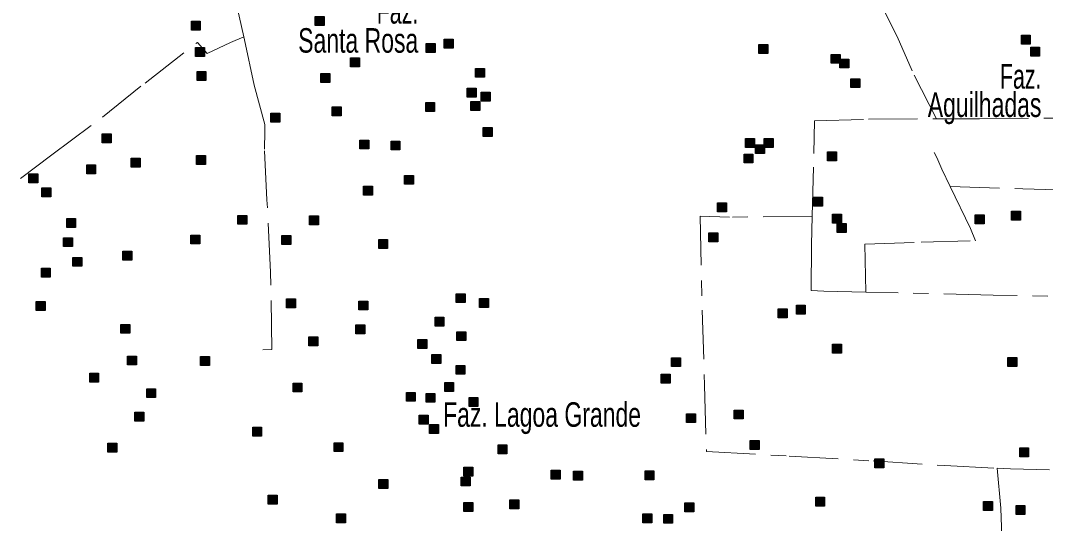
# Model space of a CAD drawing. Extents: x 445.6 to 500, y 8618.1 to 8673.4.
# Drawn here: x 485.76 to 492.44, y 8640.98 to 8644.26 of the extents above; entities that cross this region are included whole.
import ezdxf
from ezdxf.enums import TextEntityAlignment as Align

# ---------------------------------------------------------------- set-up
doc = ezdxf.new("R2010")
doc.units = 0
doc.header["$LTSCALE"] = 0.064
doc.linetypes.add('DOT_DASHED', pattern=[7.7, 5, -1.2, 0.3, -1.2])
doc.layers.add('2', color=7, linetype='Continuous', lineweight=25)
doc.layers.add('22', color=7, linetype='DOT_DASHED', lineweight=13)
doc.layers.add('61', color=7, linetype='Continuous')

msp = doc.modelspace()

# ---------------------------------------------------------------- hatches: boundary and pattern name
at = {"layer": '2'}
for points in [[(487.68, 8644.2843), (487.738, 8644.2843), (487.738, 8644.2263), (487.68, 8644.2263)], [(486.8722, 8644.2533), (486.9302, 8644.2533), (486.9302, 8644.1953), (486.8722, 8644.1953)], [(488.5211, 8644.1352), (488.5791, 8644.1352), (488.5791, 8644.0772), (488.5211, 8644.0772)], [(492.2832, 8644.1613), (492.3412, 8644.1613), (492.3412, 8644.1033), (492.2832, 8644.1033)], [(486.8998, 8644.0813), (486.9578, 8644.0813), (486.9578, 8644.0233), (486.8998, 8644.0233)], [(488.4029, 8644.1081), (488.4609, 8644.1081), (488.4609, 8644.0501), (488.4029, 8644.0501)], [(490.5725, 8644.1015), (490.6305, 8644.1015), (490.6305, 8644.0435), (490.5725, 8644.0435)], [(492.344, 8644.0834), (492.402, 8644.0834), (492.402, 8644.0254), (492.344, 8644.0254)], [(487.9103, 8644.0133), (487.9683, 8644.0133), (487.9683, 8643.9553), (487.9103, 8643.9553)], [(491.0429, 8644.037), (491.1009, 8644.037), (491.1009, 8643.979), (491.0429, 8643.979)], [(491.1003, 8644.0065), (491.1583, 8644.0065), (491.1583, 8643.9485), (491.1003, 8643.9485)], [(486.9088, 8643.9252), (486.9668, 8643.9252), (486.9668, 8643.8672), (486.9088, 8643.8672)], [(488.7243, 8643.9455), (488.7823, 8643.9455), (488.7823, 8643.8875), (488.7243, 8643.8875)], [(487.7161, 8643.9117), (487.7741, 8643.9117), (487.7741, 8643.8537), (487.7161, 8643.8537)], [(491.1712, 8643.8778), (491.2292, 8643.8778), (491.2292, 8643.8198), (491.1712, 8643.8198)], [(488.6703, 8643.8168), (488.7283, 8643.8168), (488.7283, 8643.7588), (488.6703, 8643.7588)], [(488.7615, 8643.7897), (488.8195, 8643.7897), (488.8195, 8643.7317), (488.7615, 8643.7317)], [(488.6939, 8643.7287), (488.7519, 8643.7287), (488.7519, 8643.6707), (488.6939, 8643.6707)], [(487.7904, 8643.6948), (487.8484, 8643.6948), (487.8484, 8643.6368), (487.7904, 8643.6368)], [(488.4001, 8643.7219), (488.4581, 8643.7219), (488.4581, 8643.6639), (488.4001, 8643.6639)], [(487.3899, 8643.6529), (487.4479, 8643.6529), (487.4479, 8643.5949), (487.3899, 8643.5949)], [(488.775, 8643.5593), (488.833, 8643.5593), (488.833, 8643.5013), (488.775, 8643.5013)], [(486.2907, 8643.5187), (486.3487, 8643.5187), (486.3487, 8643.4607), (486.2907, 8643.4607)], [(487.9711, 8643.478), (488.0291, 8643.478), (488.0291, 8643.42), (487.9711, 8643.42)], [(488.1737, 8643.4712), (488.2317, 8643.4712), (488.2317, 8643.4132), (488.1737, 8643.4132)], [(490.4856, 8643.4882), (490.5436, 8643.4882), (490.5436, 8643.4302), (490.4856, 8643.4302)], [(490.6072, 8643.4882), (490.6652, 8643.4882), (490.6652, 8643.4302), (490.6072, 8643.4302)], [(490.5497, 8643.4475), (490.6077, 8643.4475), (490.6077, 8643.3895), (490.5497, 8643.3895)], [(491.0192, 8643.4001), (491.0772, 8643.4001), (491.0772, 8643.3421), (491.0192, 8643.3421)], [(486.4798, 8643.3594), (486.5378, 8643.3594), (486.5378, 8643.3014), (486.4798, 8643.3014)], [(486.9054, 8643.3764), (486.9634, 8643.3764), (486.9634, 8643.3184), (486.9054, 8643.3184)], [(490.4754, 8643.3865), (490.5334, 8643.3865), (490.5334, 8643.3285), (490.4754, 8643.3285)], [(485.8128, 8643.2578), (485.8708, 8643.2578), (485.8708, 8643.1998), (485.8128, 8643.1998)], [(486.1893, 8643.3154), (486.2473, 8643.3154), (486.2473, 8643.2574), (486.1893, 8643.2574)], [(488.2616, 8643.2476), (488.3196, 8643.2476), (488.3196, 8643.1896), (488.2616, 8643.1896)], [(485.8973, 8643.1663), (485.9553, 8643.1663), (485.9553, 8643.1083), (485.8973, 8643.1083)], [(487.9947, 8643.1765), (488.0527, 8643.1765), (488.0527, 8643.1185), (487.9947, 8643.1185)], [(490.3032, 8643.0681), (490.3612, 8643.0681), (490.3612, 8643.0101), (490.3032, 8643.0101)], [(490.928, 8643.1054), (490.986, 8643.1054), (490.986, 8643.0474), (490.928, 8643.0474)], [(491.053, 8642.9936), (491.111, 8642.9936), (491.111, 8642.9356), (491.053, 8642.9356)], [(491.9828, 8642.9903), (492.0408, 8642.9903), (492.0408, 8642.9323), (491.9828, 8642.9323)], [(492.2192, 8643.014), (492.2772, 8643.014), (492.2772, 8642.956), (492.2192, 8642.956)], [(486.0594, 8642.9665), (486.1174, 8642.9665), (486.1174, 8642.9085), (486.0594, 8642.9085)], [(487.1756, 8642.9868), (487.2336, 8642.9868), (487.2336, 8642.9288), (487.1756, 8642.9288)], [(487.6418, 8642.9834), (487.6998, 8642.9834), (487.6998, 8642.9254), (487.6418, 8642.9254)], [(491.0834, 8642.9326), (491.1414, 8642.9326), (491.1414, 8642.8746), (491.0834, 8642.8746)], [(486.8683, 8642.858), (486.9263, 8642.858), (486.9263, 8642.8), (486.8683, 8642.8)], [(487.4627, 8642.8547), (487.5207, 8642.8547), (487.5207, 8642.7967), (487.4627, 8642.7967)], [(490.2458, 8642.8728), (490.3038, 8642.8728), (490.3038, 8642.8148), (490.2458, 8642.8148)], [(486.0391, 8642.8411), (486.0971, 8642.8411), (486.0971, 8642.7831), (486.0391, 8642.7831)], [(488.0933, 8642.8287), (488.1513, 8642.8287), (488.1513, 8642.7707), (488.0933, 8642.7707)], [(486.4258, 8642.753), (486.4838, 8642.753), (486.4838, 8642.695), (486.4258, 8642.695)], [(486.0999, 8642.7124), (486.1579, 8642.7124), (486.1579, 8642.6544), (486.0999, 8642.6544)], [(485.894, 8642.6421), (485.952, 8642.6421), (485.952, 8642.5841), (485.894, 8642.5841)], [(488.5993, 8642.4752), (488.6573, 8642.4752), (488.6573, 8642.4172), (488.5993, 8642.4172)], [(485.8602, 8642.425), (485.9182, 8642.425), (485.9182, 8642.367), (485.8602, 8642.367)], [(487.4931, 8642.4413), (487.5511, 8642.4413), (487.5511, 8642.3833), (487.4931, 8642.3833)], [(487.9643, 8642.4278), (488.0223, 8642.4278), (488.0223, 8642.3698), (487.9643, 8642.3698)], [(488.7513, 8642.4447), (488.8093, 8642.4447), (488.8093, 8642.3867), (488.7513, 8642.3867)], [(490.8166, 8642.4007), (490.8746, 8642.4007), (490.8746, 8642.3427), (490.8166, 8642.3427)], [(488.4609, 8642.3228), (488.5189, 8642.3228), (488.5189, 8642.2648), (488.4609, 8642.2648)], [(490.6984, 8642.377), (490.7564, 8642.377), (490.7564, 8642.319), (490.6984, 8642.319)], [(486.4123, 8642.2753), (486.4703, 8642.2753), (486.4703, 8642.2173), (486.4123, 8642.2173)], [(487.9441, 8642.2719), (488.0021, 8642.2719), (488.0021, 8642.2139), (487.9441, 8642.2139)], [(487.6384, 8642.194), (487.6964, 8642.194), (487.6964, 8642.136), (487.6384, 8642.136)], [(488.6027, 8642.2279), (488.6607, 8642.2279), (488.6607, 8642.1699), (488.6027, 8642.1699)], [(488.3494, 8642.1771), (488.4074, 8642.1771), (488.4074, 8642.1191), (488.3494, 8642.1191)], [(491.053, 8642.1466), (491.111, 8642.1466), (491.111, 8642.0886), (491.053, 8642.0886)], [(486.4562, 8642.0687), (486.5142, 8642.0687), (486.5142, 8642.0107), (486.4562, 8642.0107)], [(486.9324, 8642.0653), (486.9904, 8642.0653), (486.9904, 8642.0073), (486.9324, 8642.0073)], [(488.4406, 8642.0788), (488.4986, 8642.0788), (488.4986, 8642.0208), (488.4406, 8642.0208)], [(490.0021, 8642.0584), (490.0601, 8642.0584), (490.0601, 8642.0004), (490.0021, 8642.0004)], [(492.1958, 8642.0589), (492.2538, 8642.0589), (492.2538, 8642.0009), (492.1958, 8642.0009)], [(488.5977, 8642.0082), (488.6557, 8642.0082), (488.6557, 8641.9502), (488.5977, 8641.9502)], [(486.2092, 8641.9573), (486.2672, 8641.9573), (486.2672, 8641.8993), (486.2092, 8641.8993)], [(489.9345, 8641.9506), (489.9925, 8641.9506), (489.9925, 8641.8926), (489.9345, 8641.8926)], [(486.5807, 8641.8557), (486.6387, 8641.8557), (486.6387, 8641.7977), (486.5807, 8641.7977)], [(487.535, 8641.893), (487.593, 8641.893), (487.593, 8641.835), (487.535, 8641.835)], [(488.5234, 8641.8964), (488.5814, 8641.8964), (488.5814, 8641.8384), (488.5234, 8641.8384)], [(488.2734, 8641.832), (488.3314, 8641.832), (488.3314, 8641.774), (488.2734, 8641.774)], [(488.4018, 8641.8252), (488.4598, 8641.8252), (488.4598, 8641.7672), (488.4018, 8641.7672)], [(488.6821, 8641.7981), (488.7401, 8641.7981), (488.7401, 8641.7401), (488.6821, 8641.7401)], [(486.5035, 8641.7022), (486.5615, 8641.7022), (486.5615, 8641.6442), (486.5035, 8641.6442)], [(488.3579, 8641.6829), (488.4159, 8641.6829), (488.4159, 8641.6249), (488.3579, 8641.6249)], [(490.1, 8641.6931), (490.158, 8641.6931), (490.158, 8641.6351), (490.1, 8641.6351)], [(490.4107, 8641.7169), (490.4687, 8641.7169), (490.4687, 8641.6589), (490.4107, 8641.6589)], [(487.2716, 8641.605), (487.3296, 8641.605), (487.3296, 8641.547), (487.2716, 8641.547)], [(488.4254, 8641.6219), (488.4834, 8641.6219), (488.4834, 8641.5639), (488.4254, 8641.5639)], [(490.5154, 8641.517), (490.5734, 8641.517), (490.5734, 8641.459), (490.5154, 8641.459)], [(486.328, 8641.5), (486.386, 8641.5), (486.386, 8641.442), (486.328, 8641.442)], [(487.8019, 8641.5034), (487.8599, 8641.5034), (487.8599, 8641.4454), (487.8019, 8641.4454)], [(488.8713, 8641.4898), (488.9293, 8641.4898), (488.9293, 8641.4318), (488.8713, 8641.4318)], [(492.2725, 8641.4695), (492.3305, 8641.4695), (492.3305, 8641.4115), (492.2725, 8641.4115)], [(491.3278, 8641.3983), (491.3858, 8641.3983), (491.3858, 8641.3403), (491.3278, 8641.3403)], [(488.6483, 8641.3441), (488.7063, 8641.3441), (488.7063, 8641.2861), (488.6483, 8641.2861)], [(489.2184, 8641.3239), (489.2764, 8641.3239), (489.2764, 8641.2659), (489.2184, 8641.2659)], [(489.3636, 8641.3171), (489.4216, 8641.3171), (489.4216, 8641.2591), (489.3636, 8641.2591)], [(489.8298, 8641.3205), (489.8878, 8641.3205), (489.8878, 8641.2625), (489.8298, 8641.2625)], [(488.0944, 8641.2628), (488.1524, 8641.2628), (488.1524, 8641.2048), (488.0944, 8641.2048)], [(488.6314, 8641.2798), (488.6894, 8641.2798), (488.6894, 8641.2218), (488.6314, 8641.2218)], [(487.3729, 8641.1612), (487.4309, 8641.1612), (487.4309, 8641.1032), (487.3729, 8641.1032)], [(488.9482, 8641.1308), (489.0062, 8641.1308), (489.0062, 8641.0728), (488.9482, 8641.0728)], [(490.9427, 8641.1476), (491.0007, 8641.1476), (491.0007, 8641.0896), (490.9427, 8641.0896)], [(492.0361, 8641.1205), (492.0941, 8641.1205), (492.0941, 8641.0625), (492.0361, 8641.0625)], [(488.6483, 8641.1138), (488.7063, 8641.1138), (488.7063, 8641.0558), (488.6483, 8641.0558)], [(490.0899, 8641.1104), (490.1479, 8641.1104), (490.1479, 8641.0524), (490.0899, 8641.0524)], [(492.2489, 8641.0934), (492.3069, 8641.0934), (492.3069, 8641.0354), (492.2489, 8641.0354)], [(487.8188, 8641.0392), (487.8768, 8641.0392), (487.8768, 8640.9812), (487.8188, 8640.9812)], [(489.8163, 8641.0393), (489.8743, 8641.0393), (489.8743, 8640.9813), (489.8163, 8640.9813)], [(489.9514, 8641.0359), (490.0094, 8641.0359), (490.0094, 8640.9779), (489.9514, 8640.9779)]]:
    msp.add_hatch(color=256, dxfattribs=at).paths.add_polyline_path(points)

# ---------------------------------------------------------------- linework, layer by layer
for points in [[(487.68, 8644.2843), (487.738, 8644.2843), (487.738, 8644.2263), (487.68, 8644.2263)], [(486.8722, 8644.2533), (486.9302, 8644.2533), (486.9302, 8644.1953), (486.8722, 8644.1953)], [(488.5211, 8644.1352), (488.5791, 8644.1352), (488.5791, 8644.0772), (488.5211, 8644.0772)], [(492.2832, 8644.1613), (492.3412, 8644.1613), (492.3412, 8644.1033), (492.2832, 8644.1033)], [(486.8998, 8644.0813), (486.9578, 8644.0813), (486.9578, 8644.0233), (486.8998, 8644.0233)], [(488.4029, 8644.1081), (488.4609, 8644.1081), (488.4609, 8644.0501), (488.4029, 8644.0501)], [(490.5725, 8644.1015), (490.6305, 8644.1015), (490.6305, 8644.0435), (490.5725, 8644.0435)], [(492.344, 8644.0834), (492.402, 8644.0834), (492.402, 8644.0254), (492.344, 8644.0254)], [(487.9103, 8644.0133), (487.9683, 8644.0133), (487.9683, 8643.9553), (487.9103, 8643.9553)], [(491.0429, 8644.037), (491.1009, 8644.037), (491.1009, 8643.979), (491.0429, 8643.979)], [(491.1003, 8644.0065), (491.1583, 8644.0065), (491.1583, 8643.9485), (491.1003, 8643.9485)], [(486.9088, 8643.9252), (486.9668, 8643.9252), (486.9668, 8643.8672), (486.9088, 8643.8672)], [(488.7243, 8643.9455), (488.7823, 8643.9455), (488.7823, 8643.8875), (488.7243, 8643.8875)], [(487.7161, 8643.9117), (487.7741, 8643.9117), (487.7741, 8643.8537), (487.7161, 8643.8537)], [(491.1712, 8643.8778), (491.2292, 8643.8778), (491.2292, 8643.8198), (491.1712, 8643.8198)], [(488.6703, 8643.8168), (488.7283, 8643.8168), (488.7283, 8643.7588), (488.6703, 8643.7588)], [(488.7615, 8643.7897), (488.8195, 8643.7897), (488.8195, 8643.7317), (488.7615, 8643.7317)], [(488.6939, 8643.7287), (488.7519, 8643.7287), (488.7519, 8643.6707), (488.6939, 8643.6707)], [(487.7904, 8643.6948), (487.8484, 8643.6948), (487.8484, 8643.6368), (487.7904, 8643.6368)], [(488.4001, 8643.7219), (488.4581, 8643.7219), (488.4581, 8643.6639), (488.4001, 8643.6639)], [(487.3899, 8643.6529), (487.4479, 8643.6529), (487.4479, 8643.5949), (487.3899, 8643.5949)], [(488.775, 8643.5593), (488.833, 8643.5593), (488.833, 8643.5013), (488.775, 8643.5013)], [(486.2907, 8643.5187), (486.3487, 8643.5187), (486.3487, 8643.4607), (486.2907, 8643.4607)], [(487.9711, 8643.478), (488.0291, 8643.478), (488.0291, 8643.42), (487.9711, 8643.42)], [(488.1737, 8643.4712), (488.2317, 8643.4712), (488.2317, 8643.4132), (488.1737, 8643.4132)], [(490.4856, 8643.4882), (490.5436, 8643.4882), (490.5436, 8643.4302), (490.4856, 8643.4302)], [(490.6072, 8643.4882), (490.6652, 8643.4882), (490.6652, 8643.4302), (490.6072, 8643.4302)], [(490.5497, 8643.4475), (490.6077, 8643.4475), (490.6077, 8643.3895), (490.5497, 8643.3895)], [(491.0192, 8643.4001), (491.0772, 8643.4001), (491.0772, 8643.3421), (491.0192, 8643.3421)], [(486.4798, 8643.3594), (486.5378, 8643.3594), (486.5378, 8643.3014), (486.4798, 8643.3014)], [(486.9054, 8643.3764), (486.9634, 8643.3764), (486.9634, 8643.3184), (486.9054, 8643.3184)], [(490.4754, 8643.3865), (490.5334, 8643.3865), (490.5334, 8643.3285), (490.4754, 8643.3285)], [(485.8128, 8643.2578), (485.8708, 8643.2578), (485.8708, 8643.1998), (485.8128, 8643.1998)], [(486.1893, 8643.3154), (486.2473, 8643.3154), (486.2473, 8643.2574), (486.1893, 8643.2574)], [(488.2616, 8643.2476), (488.3196, 8643.2476), (488.3196, 8643.1896), (488.2616, 8643.1896)], [(485.8973, 8643.1663), (485.9553, 8643.1663), (485.9553, 8643.1083), (485.8973, 8643.1083)], [(487.9947, 8643.1765), (488.0527, 8643.1765), (488.0527, 8643.1185), (487.9947, 8643.1185)], [(490.3032, 8643.0681), (490.3612, 8643.0681), (490.3612, 8643.0101), (490.3032, 8643.0101)], [(490.928, 8643.1054), (490.986, 8643.1054), (490.986, 8643.0474), (490.928, 8643.0474)], [(491.053, 8642.9936), (491.111, 8642.9936), (491.111, 8642.9356), (491.053, 8642.9356)], [(491.9828, 8642.9903), (492.0408, 8642.9903), (492.0408, 8642.9323), (491.9828, 8642.9323)], [(492.2192, 8643.014), (492.2772, 8643.014), (492.2772, 8642.956), (492.2192, 8642.956)], [(486.0594, 8642.9665), (486.1174, 8642.9665), (486.1174, 8642.9085), (486.0594, 8642.9085)], [(487.1756, 8642.9868), (487.2336, 8642.9868), (487.2336, 8642.9288), (487.1756, 8642.9288)], [(487.6418, 8642.9834), (487.6998, 8642.9834), (487.6998, 8642.9254), (487.6418, 8642.9254)], [(491.0834, 8642.9326), (491.1414, 8642.9326), (491.1414, 8642.8746), (491.0834, 8642.8746)], [(486.8683, 8642.858), (486.9263, 8642.858), (486.9263, 8642.8), (486.8683, 8642.8)], [(487.4627, 8642.8547), (487.5207, 8642.8547), (487.5207, 8642.7967), (487.4627, 8642.7967)], [(490.2458, 8642.8728), (490.3038, 8642.8728), (490.3038, 8642.8148), (490.2458, 8642.8148)], [(486.0391, 8642.8411), (486.0971, 8642.8411), (486.0971, 8642.7831), (486.0391, 8642.7831)], [(488.0933, 8642.8287), (488.1513, 8642.8287), (488.1513, 8642.7707), (488.0933, 8642.7707)], [(486.4258, 8642.753), (486.4838, 8642.753), (486.4838, 8642.695), (486.4258, 8642.695)], [(486.0999, 8642.7124), (486.1579, 8642.7124), (486.1579, 8642.6544), (486.0999, 8642.6544)], [(485.894, 8642.6421), (485.952, 8642.6421), (485.952, 8642.5841), (485.894, 8642.5841)], [(488.5993, 8642.4752), (488.6573, 8642.4752), (488.6573, 8642.4172), (488.5993, 8642.4172)], [(485.8602, 8642.425), (485.9182, 8642.425), (485.9182, 8642.367), (485.8602, 8642.367)], [(487.4931, 8642.4413), (487.5511, 8642.4413), (487.5511, 8642.3833), (487.4931, 8642.3833)], [(487.9643, 8642.4278), (488.0223, 8642.4278), (488.0223, 8642.3698), (487.9643, 8642.3698)], [(488.7513, 8642.4447), (488.8093, 8642.4447), (488.8093, 8642.3867), (488.7513, 8642.3867)], [(490.8166, 8642.4007), (490.8746, 8642.4007), (490.8746, 8642.3427), (490.8166, 8642.3427)], [(488.4609, 8642.3228), (488.5189, 8642.3228), (488.5189, 8642.2648), (488.4609, 8642.2648)], [(490.6984, 8642.377), (490.7564, 8642.377), (490.7564, 8642.319), (490.6984, 8642.319)], [(486.4123, 8642.2753), (486.4703, 8642.2753), (486.4703, 8642.2173), (486.4123, 8642.2173)], [(487.9441, 8642.2719), (488.0021, 8642.2719), (488.0021, 8642.2139), (487.9441, 8642.2139)], [(487.6384, 8642.194), (487.6964, 8642.194), (487.6964, 8642.136), (487.6384, 8642.136)], [(488.6027, 8642.2279), (488.6607, 8642.2279), (488.6607, 8642.1699), (488.6027, 8642.1699)], [(488.3494, 8642.1771), (488.4074, 8642.1771), (488.4074, 8642.1191), (488.3494, 8642.1191)], [(491.053, 8642.1466), (491.111, 8642.1466), (491.111, 8642.0886), (491.053, 8642.0886)], [(486.4562, 8642.0687), (486.5142, 8642.0687), (486.5142, 8642.0107), (486.4562, 8642.0107)], [(486.9324, 8642.0653), (486.9904, 8642.0653), (486.9904, 8642.0073), (486.9324, 8642.0073)], [(488.4406, 8642.0788), (488.4986, 8642.0788), (488.4986, 8642.0208), (488.4406, 8642.0208)], [(490.0021, 8642.0584), (490.0601, 8642.0584), (490.0601, 8642.0004), (490.0021, 8642.0004)], [(492.1958, 8642.0589), (492.2538, 8642.0589), (492.2538, 8642.0009), (492.1958, 8642.0009)], [(488.5977, 8642.0082), (488.6557, 8642.0082), (488.6557, 8641.9502), (488.5977, 8641.9502)], [(486.2092, 8641.9573), (486.2672, 8641.9573), (486.2672, 8641.8993), (486.2092, 8641.8993)], [(489.9345, 8641.9506), (489.9925, 8641.9506), (489.9925, 8641.8926), (489.9345, 8641.8926)], [(486.5807, 8641.8557), (486.6387, 8641.8557), (486.6387, 8641.7977), (486.5807, 8641.7977)], [(487.535, 8641.893), (487.593, 8641.893), (487.593, 8641.835), (487.535, 8641.835)], [(488.5234, 8641.8964), (488.5814, 8641.8964), (488.5814, 8641.8384), (488.5234, 8641.8384)], [(488.2734, 8641.832), (488.3314, 8641.832), (488.3314, 8641.774), (488.2734, 8641.774)], [(488.4018, 8641.8252), (488.4598, 8641.8252), (488.4598, 8641.7672), (488.4018, 8641.7672)], [(488.6821, 8641.7981), (488.7401, 8641.7981), (488.7401, 8641.7401), (488.6821, 8641.7401)], [(486.5035, 8641.7022), (486.5615, 8641.7022), (486.5615, 8641.6442), (486.5035, 8641.6442)], [(488.3579, 8641.6829), (488.4159, 8641.6829), (488.4159, 8641.6249), (488.3579, 8641.6249)], [(490.1, 8641.6931), (490.158, 8641.6931), (490.158, 8641.6351), (490.1, 8641.6351)], [(490.4107, 8641.7169), (490.4687, 8641.7169), (490.4687, 8641.6589), (490.4107, 8641.6589)], [(487.2716, 8641.605), (487.3296, 8641.605), (487.3296, 8641.547), (487.2716, 8641.547)], [(488.4254, 8641.6219), (488.4834, 8641.6219), (488.4834, 8641.5639), (488.4254, 8641.5639)], [(490.5154, 8641.517), (490.5734, 8641.517), (490.5734, 8641.459), (490.5154, 8641.459)], [(486.328, 8641.5), (486.386, 8641.5), (486.386, 8641.442), (486.328, 8641.442)], [(487.8019, 8641.5034), (487.8599, 8641.5034), (487.8599, 8641.4454), (487.8019, 8641.4454)], [(488.8713, 8641.4898), (488.9293, 8641.4898), (488.9293, 8641.4318), (488.8713, 8641.4318)], [(492.2725, 8641.4695), (492.3305, 8641.4695), (492.3305, 8641.4115), (492.2725, 8641.4115)], [(491.3278, 8641.3983), (491.3858, 8641.3983), (491.3858, 8641.3403), (491.3278, 8641.3403)], [(488.6483, 8641.3441), (488.7063, 8641.3441), (488.7063, 8641.2861), (488.6483, 8641.2861)], [(489.2184, 8641.3239), (489.2764, 8641.3239), (489.2764, 8641.2659), (489.2184, 8641.2659)], [(489.3636, 8641.3171), (489.4216, 8641.3171), (489.4216, 8641.2591), (489.3636, 8641.2591)], [(489.8298, 8641.3205), (489.8878, 8641.3205), (489.8878, 8641.2625), (489.8298, 8641.2625)], [(488.0944, 8641.2628), (488.1524, 8641.2628), (488.1524, 8641.2048), (488.0944, 8641.2048)], [(488.6314, 8641.2798), (488.6894, 8641.2798), (488.6894, 8641.2218), (488.6314, 8641.2218)], [(487.3729, 8641.1612), (487.4309, 8641.1612), (487.4309, 8641.1032), (487.3729, 8641.1032)], [(488.9482, 8641.1308), (489.0062, 8641.1308), (489.0062, 8641.0728), (488.9482, 8641.0728)], [(490.9427, 8641.1476), (491.0007, 8641.1476), (491.0007, 8641.0896), (490.9427, 8641.0896)], [(492.0361, 8641.1205), (492.0941, 8641.1205), (492.0941, 8641.0625), (492.0361, 8641.0625)], [(488.6483, 8641.1138), (488.7063, 8641.1138), (488.7063, 8641.0558), (488.6483, 8641.0558)], [(490.0899, 8641.1104), (490.1479, 8641.1104), (490.1479, 8641.0524), (490.0899, 8641.0524)], [(492.2489, 8641.0934), (492.3069, 8641.0934), (492.3069, 8641.0354), (492.2489, 8641.0354)], [(487.8188, 8641.0392), (487.8768, 8641.0392), (487.8768, 8640.9812), (487.8188, 8640.9812)], [(489.8163, 8641.0393), (489.8743, 8641.0393), (489.8743, 8640.9813), (489.8163, 8640.9813)], [(489.9514, 8641.0359), (490.0094, 8641.0359), (490.0094, 8640.9779), (489.9514, 8640.9779)]]:
    msp.add_lwpolyline(points, close=True, dxfattribs=at)
at = {"layer": '22'}
for points in [[(491.7306, 8643.6161), (491.5707, 8643.93), (491.4727, 8644.1533), (491.2838, 8644.5343), (491.1747, 8644.7557), (491.4182, 8644.879), (491.887, 8645.1367), (492.0257, 8645.2002), (492.066, 8645.2261)], [(487.2145, 8644.1516), (487.1681, 8644.3542), (487.1223, 8644.5448), (486.883, 8644.5529), (486.7136, 8644.5663), (486.649, 8644.4911), (486.64, 8644.4852)], [(485.7578, 8643.2278), (485.9631, 8643.3807), (486.2935, 8643.628), (486.5698, 8643.85), (486.9118, 8644.1151), (486.9753, 8644.0421), (487.1277, 8644.1151), (487.2145, 8644.1516)], [(487.3388, 8642.1086), (487.3967, 8642.112), (487.3887, 8642.6168), (487.3645, 8643.0885), (487.3483, 8643.4188), (487.351, 8643.5343), (487.351, 8643.5793), (487.2811, 8643.8371), (487.2192, 8644.1313), (487.2145, 8644.1516)], [(490.9203, 8642.9811), (490.9304, 8643.3907), (490.934, 8643.603), (491.2865, 8643.6139), (491.7306, 8643.6161)], [(491.7306, 8643.6161), (492.0097, 8643.6175), (492.5535, 8643.6214), (492.7134, 8643.625)], [(491.8199, 8643.1742), (491.7654, 8643.2875), (491.7315, 8643.3635), (491.7155, 8643.3977)], [(491.27, 8642.4863), (491.2637, 8642.7989), (491.6291, 8642.8113), (491.9852, 8642.8206), (491.9512, 8642.901), (491.8199, 8643.1742)], [(491.8199, 8643.1742), (492.292, 8643.1594), (492.7194, 8643.1471), (493.2629, 8643.1402), (493.7336, 8643.1309), (493.9101, 8643.1247), (494.0192, 8643.1241)], [(490.9203, 8642.9811), (490.3794, 8642.9749), (490.1901, 8642.9811), (490.2025, 8642.3676), (490.2179, 8641.8792), (490.2302, 8641.4469), (490.7701, 8641.4159), (491.3162, 8641.3849), (491.7839, 8641.3539), (492.126, 8641.3366)], [(491.27, 8642.4863), (490.9957, 8642.4926), (490.9121, 8642.4962), (490.9157, 8642.7938), (490.9203, 8642.9811)], [(493.8486, 8642.5325), (493.8342, 8642.5262), (493.46, 8642.3738), (493.38, 8642.4246), (493.2238, 8642.4826), (493.1983, 8642.4391), (492.8749, 8642.45), (492.0987, 8642.4669), (491.481, 8642.4815), (491.27, 8642.4863)], [(492.126, 8641.3366), (492.2121, 8641.3322), (492.4665, 8641.326)], [(492.2015, 8639.8708), (492.1908, 8640.1759), (492.1763, 8640.4808), (492.1595, 8640.8113), (492.1499, 8641.0777), (492.126, 8641.3366)]]:
    msp.add_lwpolyline(points, dxfattribs=at)

# ---------------------------------------------------------------- texts
at = {"layer": '61'}
for s, width, p in [('Faz.', 0.65, (488.351, 8644.2379)), ('Santa Rosa', 0.7, (488.351, 8644.0479)), ('Faz.', 0.65, (492.4142, 8643.8136)), ('Aguilhadas', 0.7, (492.4142, 8643.6286))]:
    msp.add_text(s, height=0.16, dxfattribs=dict(at, width=width)).set_placement(p, align=Align.RIGHT)
at = {"layer": '61', "width": 0.7}
msp.add_text('Faz. Lagoa Grande', height=0.16, dxfattribs=at).set_placement((488.5129, 8641.6075))

doc.saveas('drawing.dxf')
